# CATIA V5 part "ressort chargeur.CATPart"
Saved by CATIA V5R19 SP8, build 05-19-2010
Part number: ressort chargeur
Bounding box of the stored display mesh (mm): x -13.25 to 13.25, y -3.681 to 16.819, z -8.75 to 8.75
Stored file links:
  C:\Users\Arthur\Desktop\Catia parts\GLOCK\ressort chargeur.CATPart
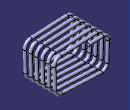
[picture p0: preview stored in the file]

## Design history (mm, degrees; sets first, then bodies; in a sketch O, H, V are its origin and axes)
Set1
  Sketch1 on zx-plane, origin (0, 0, 0), H (-1, 0, 0), V (0, 0, 1)
    line L1 (12.5, 8) -> (12.5, -8)
    line L2 (12.5, -8) -> (-12.5, -8)
    line L3 (-12.5, -8) -> (-12.5, 8)
    line L4 (-12.5, 8) -> (12.5, 8)
    length L4 = 25
    length L1 = 16
    vertical: L1 V, L3 V
    horizontal: L2 H, L4 H
    equidistance: L1 L3 O, L2 L4 O
  Extrude1: Element1 Sketch1, Lim1 19, Lim2 0
  Fillet1: radius 3, on edge [face of Extrude1 from Sketch1.L1 | face of Extrude1 from Sketch1.L4]; edge [face of Extrude1 from Sketch1.L2 | face of Extrude1 from Sketch1.L1]; edge [face of Extrude1 from Sketch1.L3 | face of Extrude1 from Sketch1.L2]; edge [face of Extrude1 from Sketch1.L4 | face of Extrude1 from Sketch1.L3]
  Sketch2 on yz-plane, origin (0, 0, 0), H (0, 1, 0), V (0, 0, 1)
    line L1 (0, 19.6002) -> (0, -18.1793)
    point P1 (0, 19.6002)
    coincidence: P1 V
    vertical: L1 V
  Sweep1: type Unspec, Profile Sketch2, Guide Sketch3, Reference yz-plane, RefAngle 0, RefAngle2 3000
  Sketch3 on yz-plane, origin (0, 0, 0), H (0, 1, 0), V (0, 0, 1)
    line L1 (20.5948, 0) -> (-3.9388, 0)
    point P1 (20.5948, 0)
    coincidence: P1 H
    horizontal: L1 H
  Intersect1: ToIntersect1 Sweep1, ToIntersect2 Fillet1
  Extract1: ExtractElem edge of Intersect1
  Sketch4 on yz-plane, origin (0, 0, 0), H (0, 1, 0), V (0, 0, 1)
    circle A1 centre (0, -8) radius 0.75
    point P1 (0, -8)
    reference projected point E1 (0, -8) from vertex of Intersect1
    radius A1 = 0.75
    coincidence: P1 V, P1 E1
Body1 (main body)
  Rib1: profile Sketch4, centre curve Extract1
